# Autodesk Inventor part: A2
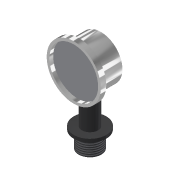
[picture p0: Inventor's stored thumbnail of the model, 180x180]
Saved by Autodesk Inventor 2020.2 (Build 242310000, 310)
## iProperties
Created: 2014-08
Part Number: A2
Material: Ogólny
Document SubType Name: Modeling
Designer: F.Stasiak
Density: 1 g/cm^3
Appearance: Domyślna
Categories: <MemberInstance><Categories><Category DisplayName="" InternalName="4347fa0f-2144-441d-94cd-e3e15c92b736" Mnemonic="TUBEANDPIPE"><CategoryParameter DisplayName="
Catalog Web Link: www.expertbooks.pl
Manager: www.cadconsulting.pl
Company: Fabian Stasiak CAD Consulting
Author: F.Stasiak
Subject: Zbiór ćwiczeń. Autodesk Inventor 2020. Kurs Professional
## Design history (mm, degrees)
sketch "Szkic1"
  geometry: C1 r 10.45 at (0, 0); 1 further point
  constraints: 1 centre point, 1 coincident
  dimensions: "d0" = 20.9 diameter of C1
extrude "Wyciągnięcie proste1" new body sketch "Szkic1" distance "d1" = 15; taper "d2" = 0 deg
sketch "Szkic2"
  geometry: C1 r 15 at (0, 0); 1 further point
  constraints: 1 centre point, 1 coincident
  dimensions: "d3" = 30 diameter of C1
extrude "Wyciągnięcie proste2" join sketch "Szkic2" distance "d4" = 3; taper "d5" = 0 deg
sketch "Szkic3"
  geometry: C1 r 7.5 at (0, 0); 1 further point
  constraints: 1 centre point, 1 coincident
  dimensions: "d6" = 15 diameter of C1
extrude "Wyciągnięcie proste3" join sketch "Szkic3" distance "d7" = 50; taper "d8" = 0 deg
sketch "Szkic4"
  geometry: L1 (7.5, 68)-(-7.5, 68) reference; C1 r 20 at (0, 68); 1 further point
  constraints: 1 centre point, 1 midpoint
  dimensions: "d9" = 40 diameter of C1
extrude "Wyciągnięcie proste4" join sketch "Szkic4" stored distance "d10" = 20; taper "d11" = 0 deg
sketch "Szkic5"
  geometry: C1 r 20 at (0, 0) reference; C2 r 25 at (0, 0); 1 further point
  constraints: 1 centre point, 1 coincident
  dimensions: "d12" = 50 diameter of C2
extrude "Wyciągnięcie proste5" join sketch "Szkic5" distance "d13" = 5; taper "d14" = 0 deg
chamfer "Faza1" distance "d15" = 2; stored, may be unused: second distance "d16" = 2, angle "d17" = 45 deg
sketch "Szkic6"
  geometry: C1 r 25 at (0, 0) reference; C2 r 22.5 at (0, 0); 1 further point
  constraints: 1 centre point, 1 coincident
  dimensions: "d18" = 45 diameter of C2
extrude "Wyciągnięcie proste6" cut sketch "Szkic6" distance "d19" = 3.5; taper "d20" = 0 deg
sketch "Szkic7"
  geometry: C1 r 5 at (0, 0); 1 further point
  constraints: 1 centre point, 1 coincident
  dimensions: "d21" = 10 diameter of C1
extrude "Wyciągnięcie proste7" cut sketch "Szkic7" distance "d22" = 52; taper "d23" = 0 deg
feature "Gwint2" dims "d26" = 10, "d27" = 0
node "Punkt konstrukcyjny1"
node "Oś konstrukcyjna1"
node "Bryła1"
node "Pętla rzutowana1"
node "Pętla rzutowana2"
